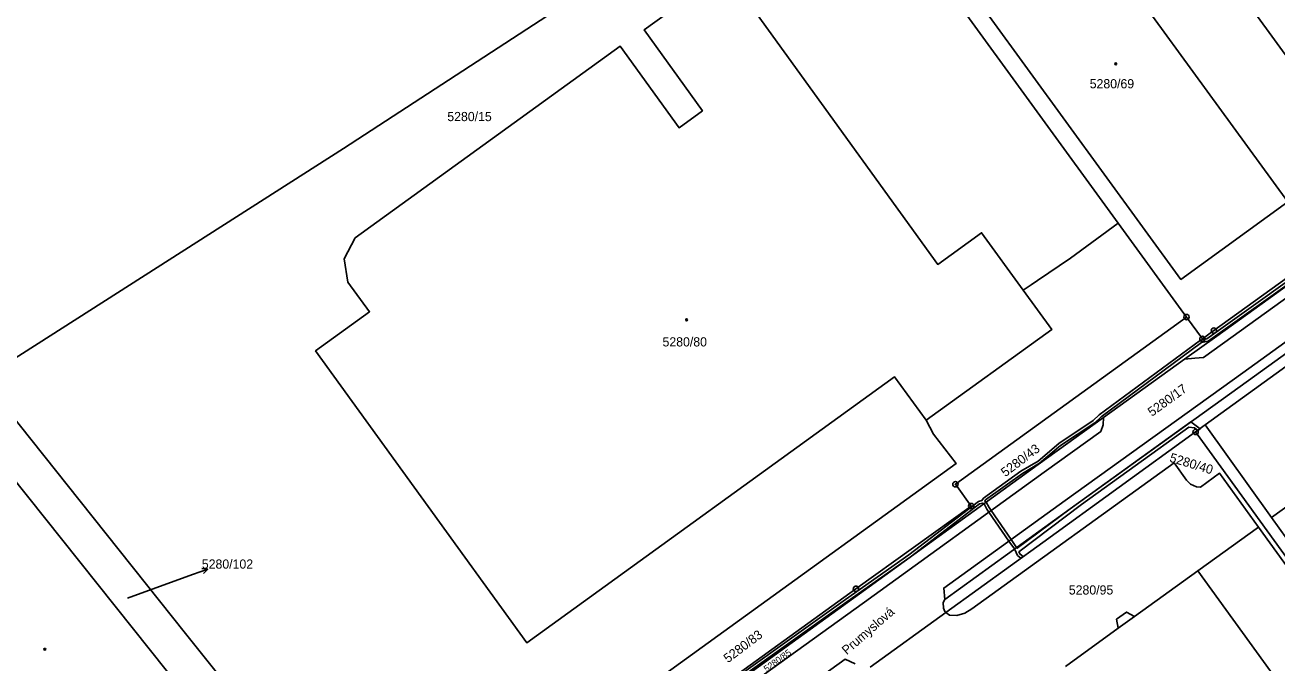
# Model space of a CAD drawing. Extents: x -644096 to -634268, y -1141430 to -1133463.
# Drawn here: x -637778.1 to -637546.6, y -1139923.7 to -1139805.7 of the extents above; entities that cross this region are included whole.
import ezdxf

# ---------------------------------------------------------------- set-up
doc = ezdxf.new("R2010")
doc.units = 0
for name, color, linetype in [('_CIVIL_CONSTRUCTION', 7, 'Continuous'), ('B_Hranice _3D', 7, 'Continuous'), ('M_Svah_Nasyp', 7, 'Continuous'), ('M_Svah_Zarez', 7, 'Continuous'), ('svrsek_osa_VRT', 7, 'Continuous'), ('svrsek_popisy_VRT', 7, 'Continuous'), ('terminal_VRT', 7, 'Continuous')]:
    doc.layers.add(name, color=color, linetype=linetype)

msp = doc.modelspace()

# ---------------------------------------------------------------- linework, layer by layer
at = {"layer": '_CIVIL_CONSTRUCTION'}
for centre, radius in [((-637563.31, -1139859.73), 0.5), ((-637563.31, -1139859.73), 0.0303), ((-637558.24, -1139862.24), 0.5), ((-637558.24, -1139862.24), 0.0303), ((-637560.37, -1139863.78), 0.5), ((-637560.37, -1139863.78), 0.0303), ((-637561.63, -1139880.98), 0.5), ((-637561.63, -1139880.98), 0.0303), ((-637606.05, -1139890.66), 0.5), ((-637606.05, -1139890.66), 0.0303), ((-637603.12, -1139894.71), 0.5), ((-637603.12, -1139894.71), 0.0303), ((-637624.44, -1139910), 0.5), ((-637624.44, -1139910), 0.0303)]:
    msp.add_circle(centre, radius, dxfattribs=at)
at = {"layer": 'B_Hranice _3D'}
for points in [[(-637536.01, -1139846.93), (-637559.52, -1139863.75), (-637560.73, -1139864), (-637579.43, -1139877.79), (-637580.56, -1139878.89), (-637586.92, -1139883.11), (-637590.77, -1139886.38), (-637593.92, -1139888.26), (-637600.82, -1139893.21), (-637601.14, -1139893.66), (-637601.79, -1139893.85), (-637614.68, -1139903.74), (-637626.38, -1139912), (-637654.66, -1139932.19)], [(-637654.36, -1139932.59), (-637626.1, -1139912.4), (-637614.4, -1139904.12), (-637601.57, -1139894.31), (-637601.01, -1139894.15), (-637600.75, -1139894.27), (-637600.25, -1139895.24), (-637599.84, -1139895.82), (-637596.14, -1139901.16), (-637595.12, -1139902.63), (-637595.05, -1139902.73), (-637594.55, -1139903.82), (-637593.96, -1139904.35), (-637593.54, -1139904.05), (-637594.09, -1139903.62), (-637594.29, -1139903.19), (-637582.75, -1139894.41), (-637562.87, -1139880.1), (-637561.83, -1139880.24), (-637561.22, -1139880.69), (-637560.8, -1139880.38), (-637562.5, -1139879.12), (-637584.8, -1139895.18), (-637594.61, -1139902.49), (-637594.72, -1139902.34), (-637595.74, -1139900.87), (-637599.44, -1139895.54), (-637599.83, -1139894.98), (-637600.35, -1139893.97), (-637600.39, -1139893.89), (-637600.61, -1139893.78), (-637600.46, -1139893.57), (-637593.64, -1139888.68), (-637590.47, -1139886.78), (-637586.62, -1139883.51), (-637580.24, -1139879.29), (-637579.11, -1139878.17), (-637560.53, -1139864.46), (-637559.32, -1139864.21), (-637535.71, -1139847.33)]]:
    msp.add_lwpolyline(points, dxfattribs=at)
at = {"layer": 'M_Svah_Nasyp'}
msp.add_line((-637572.93, -1139915.12), (-637575.93, -1139917.27), dxfattribs=at)
at = {"layer": 'M_Svah_Zarez'}
for centre in [(-637576.4, -1139812.88), (-637655.75, -1139860.23), (-637774.46, -1139921.19)]:
    msp.add_circle(centre, 0.175, dxfattribs=at)
at = {"layer": 'svrsek_popisy_VRT'}
for p, q in [((-637747.14, -1139907.37), (-637744.32, -1139906.34)), ((-637744.32, -1139906.34), (-637745.43, -1139906.22)), ((-637744.32, -1139906.34), (-637745.09, -1139907.16)), ((-637759.17, -1139911.76), (-637747.14, -1139907.37))]:
    msp.add_line(p, q, dxfattribs=at)
at = {"layer": 'terminal_VRT'}
for p, q in [((-637575.93, -1139842.37), (-637629.33, -1139768.92)), ((-637563.31, -1139859.73), (-637575.93, -1139842.37)), ((-637563.66, -1139867.54), (-637578.64, -1139878.33)), ((-637559.85, -1139879.69), (-637543.8, -1139868.09)), ((-637561.63, -1139880.98), (-637559.85, -1139879.69)), ((-637559.85, -1139879.69), (-637547.62, -1139896.82)), ((-637550.02, -1139898.57), (-637561.22, -1139906.66)), ((-637621.84, -1139924.51), (-637607.8, -1139914.36))]:
    msp.add_line(p, q, dxfattribs=at)
for points in [[(-637274.21, -1139581.12), (-637274.21, -1139581.91), (-637276.65, -1139586.29), (-637285.33, -1139597.2), (-637296.64, -1139611.4), (-637311.95, -1139631.96), (-637320.38, -1139644.21), (-637343.35, -1139677.47), (-637350.4, -1139687.43), (-637367.28, -1139710.32), (-637379.91, -1139725.35), (-637394.85, -1139741.12), (-637404.78, -1139750.77), (-637424.76, -1139768.25), (-637438.92, -1139779.51), (-637457.51, -1139793.19), (-637490.64, -1139817.09), (-637523.45, -1139840.79), (-637556.64, -1139864.68), (-637560.15, -1139867.2), (-637561.78, -1139867.36), (-637563.66, -1139867.54)], [(-637608.03, -1139911.95), (-637608.2, -1139909.86), (-637585.73, -1139893.65), (-637552.9, -1139870.02), (-637519.63, -1139846.03), (-637486.56, -1139822.15), (-637453.81, -1139798.57), (-637435.12, -1139784.76), (-637420.63, -1139773.3), (-637399.74, -1139754.98), (-637390.1, -1139745.68), (-637373.78, -1139728.2), (-637370.48, -1139724.26), (-637362.19, -1139714.36), (-637357.96, -1139708.61), (-637345.2, -1139691.27), (-637338.03, -1139681.16), (-637319.25, -1139653.98), (-637318.56, -1139653.6), (-637317.63, -1139653.28), (-637316.49, -1139653.09)], [(-637608.03, -1139911.95), (-637584.8, -1139895.18), (-637551.87, -1139871.46), (-637518.59, -1139847.5), (-637485.32, -1139823.5), (-637471.35, -1139813.43), (-637452.81, -1139800.07), (-637434.04, -1139786.14), (-637419.39, -1139774.62), (-637398.57, -1139756.28), (-637388.95, -1139747), (-637373.51, -1139730.63), (-637367.84, -1139723.87), (-637360.78, -1139715.45), (-637358.13, -1139711.85), (-637343.69, -1139692.21), (-637336.55, -1139682.18), (-637316.49, -1139653.09)], [(-637368.71, -1139709.25), (-637384.23, -1139727.49), (-637396.06, -1139739.86), (-637406.06, -1139749.45), (-637425.8, -1139766.84), (-637440.06, -1139778.07), (-637458.5, -1139791.75), (-637491.7, -1139815.7), (-637524.62, -1139839.42), (-637557.7, -1139863.25), (-637563.66, -1139867.54)], [(-637586.87, -1139753.7), (-637579.78, -1139763.45), (-637525.21, -1139838.43)], [(-637544.58, -1139838.41), (-637587.15, -1139779.88), (-637606.9, -1139794.24), (-637564.33, -1139852.78), (-637544.58, -1139838.41)], [(-637785.99, -1139871.17), (-637719.21, -1139828.57), (-637690.63, -1139809.95), (-637647.49, -1139781.84)], [(-637611.46, -1139878.83), (-637617.3, -1139870.82), (-637685.29, -1139920.01), (-637724.38, -1139865.99), (-637714.37, -1139858.75), (-637718.38, -1139853.26), (-637719.08, -1139848.96), (-637717.07, -1139845.09), (-637668.02, -1139809.65), (-637657.14, -1139824.7), (-637652.82, -1139821.58), (-637663.63, -1139806.62), (-637648.53, -1139795.68), (-637637.74, -1139810.69), (-637609.32, -1139849.99), (-637601.19, -1139844.15), (-637593.51, -1139854.77)], [(-637525.21, -1139838.43), (-637558.24, -1139862.24), (-637560.37, -1139863.78), (-637563.31, -1139859.73)], [(-637593.51, -1139854.77), (-637592.05, -1139853.76), (-637590.86, -1139852.94), (-637584.78, -1139848.82), (-637575.93, -1139842.37)], [(-637611.46, -1139878.83), (-637588.24, -1139862.06), (-637593.51, -1139854.77)], [(-637563.31, -1139859.73), (-637606.05, -1139890.66), (-637603.12, -1139894.71), (-637624.44, -1139910), (-637657.31, -1139933.74), (-637691.33, -1139958.27), (-637706.78, -1139970.37)], [(-637785.99, -1139871.17), (-637767.92, -1139893.81), (-637748.41, -1139918.24), (-637727.28, -1139944.7), (-637712.12, -1139963.68)], [(-637716.72, -1139969.42), (-637724.03, -1139960.26), (-637726.12, -1139961.91), (-637727.06, -1139960.74), (-637724.96, -1139959), (-637730.36, -1139952.34), (-637742.05, -1139937.53), (-637787.38, -1139880.71), (-637793.07, -1139885.25), (-637793.55, -1139884.78), (-637787.97, -1139880.31), (-637792.06, -1139875.21)], [(-637712.12, -1139963.68), (-637673.58, -1139935.78), (-637648.87, -1139917.91), (-637605.89, -1139886.8), (-637610.08, -1139881.37), (-637611.46, -1139878.83)], [(-637696.28, -1139963.54), (-637690.61, -1139959.25), (-637674.44, -1139947.46), (-637656.73, -1139934.73), (-637623.8, -1139910.91), (-637590.73, -1139887.03), (-637578.64, -1139878.33)], [(-637578.64, -1139878.33), (-637578.74, -1139879.67), (-637579.14, -1139880.88), (-637589.62, -1139888.43), (-637622.83, -1139912.45), (-637655.64, -1139936.08), (-637675.49, -1139950.48), (-637689.7, -1139960.76), (-637693.39, -1139963.56), (-637695.12, -1139963.7), (-637696.28, -1139963.54)], [(-637607.8, -1139914.36), (-637589.9, -1139901.42), (-637561.63, -1139880.98)], [(-637500.88, -1139964.99), (-637531.26, -1139922.98), (-637561.63, -1139880.98)], [(-637607.8, -1139914.36), (-637607.13, -1139914.85), (-637605.78, -1139914.94), (-637604.3, -1139914.52), (-637603, -1139913.73), (-637565.6, -1139886.72), (-637563.33, -1139889.9), (-637562.55, -1139890.62), (-637561.45, -1139891.13), (-637560.74, -1139891.23), (-637557.2, -1139888.64), (-637550.02, -1139898.57)], [(-637547.62, -1139896.82), (-637536.2, -1139888.59), (-637536.03, -1139888.83)], [(-637547.62, -1139896.82), (-637543.36, -1139902.75), (-637525.52, -1139927.4), (-637515.21, -1139941.95)], [(-637550.02, -1139898.57), (-637501.94, -1139965.06), (-637501.74, -1139965.55)], [(-637561.22, -1139906.66), (-637572.93, -1139915.12), (-637574.42, -1139914.32), (-637576.23, -1139915.63), (-637575.93, -1139917.27), (-637585.7, -1139924.35)], [(-637546.69, -1139978.3), (-637522.21, -1139960.58), (-637561.22, -1139906.66)], [(-637607.8, -1139914.36), (-637607.98, -1139914.22), (-637608.26, -1139913.59), (-637608.29, -1139912.53), (-637608.03, -1139911.95)], [(-637741.21, -1140011.97), (-637737.73, -1140006.87), (-637717.41, -1139990.27), (-637703.62, -1139979.41), (-637685.77, -1139965.92), (-637672.15, -1139956.04), (-637651.6, -1139941.17), (-637626.45, -1139923.02), (-637624.56, -1139923.88)]]:
    msp.add_lwpolyline(points, dxfattribs=at)

# ---------------------------------------------------------------- texts
at = {"layer": 'svrsek_osa_VRT'}
for s, p in [('5280/69', (-637581.21, -1139817.42)), ('5280/15', (-637700.01, -1139823.49)), ('5280/80', (-637660.21, -1139865.17)), ('5280/102', (-637745.41, -1139906.27)), ('5280/95', (-637585.07, -1139911.06))]:
    msp.add_text(s, height=1.7, dxfattribs=at).set_placement(p)
for s, height, rotation, p in [('5280/17', 1.7, 36, (-637569.7, -1139878.2)), ('5280/43', 1.7, 37, (-637596.82, -1139889.37)), ('5280/40', 1.7, 343, (-637566.57, -1139886.45)), ('5280/83', 1.7, 37, (-637648.11, -1139923.78)), ('5280/85', 1.2, 36, (-637640.96, -1139925.46))]:
    msp.add_text(s, height=height, rotation=rotation, dxfattribs=at).set_placement(p)
at = {"layer": 'svrsek_popisy_VRT'}
msp.add_text('Prumyslová', height=1.7, rotation=41, dxfattribs=at).set_placement((-637626.14, -1139922.3))

doc.saveas('drawing.dxf')
